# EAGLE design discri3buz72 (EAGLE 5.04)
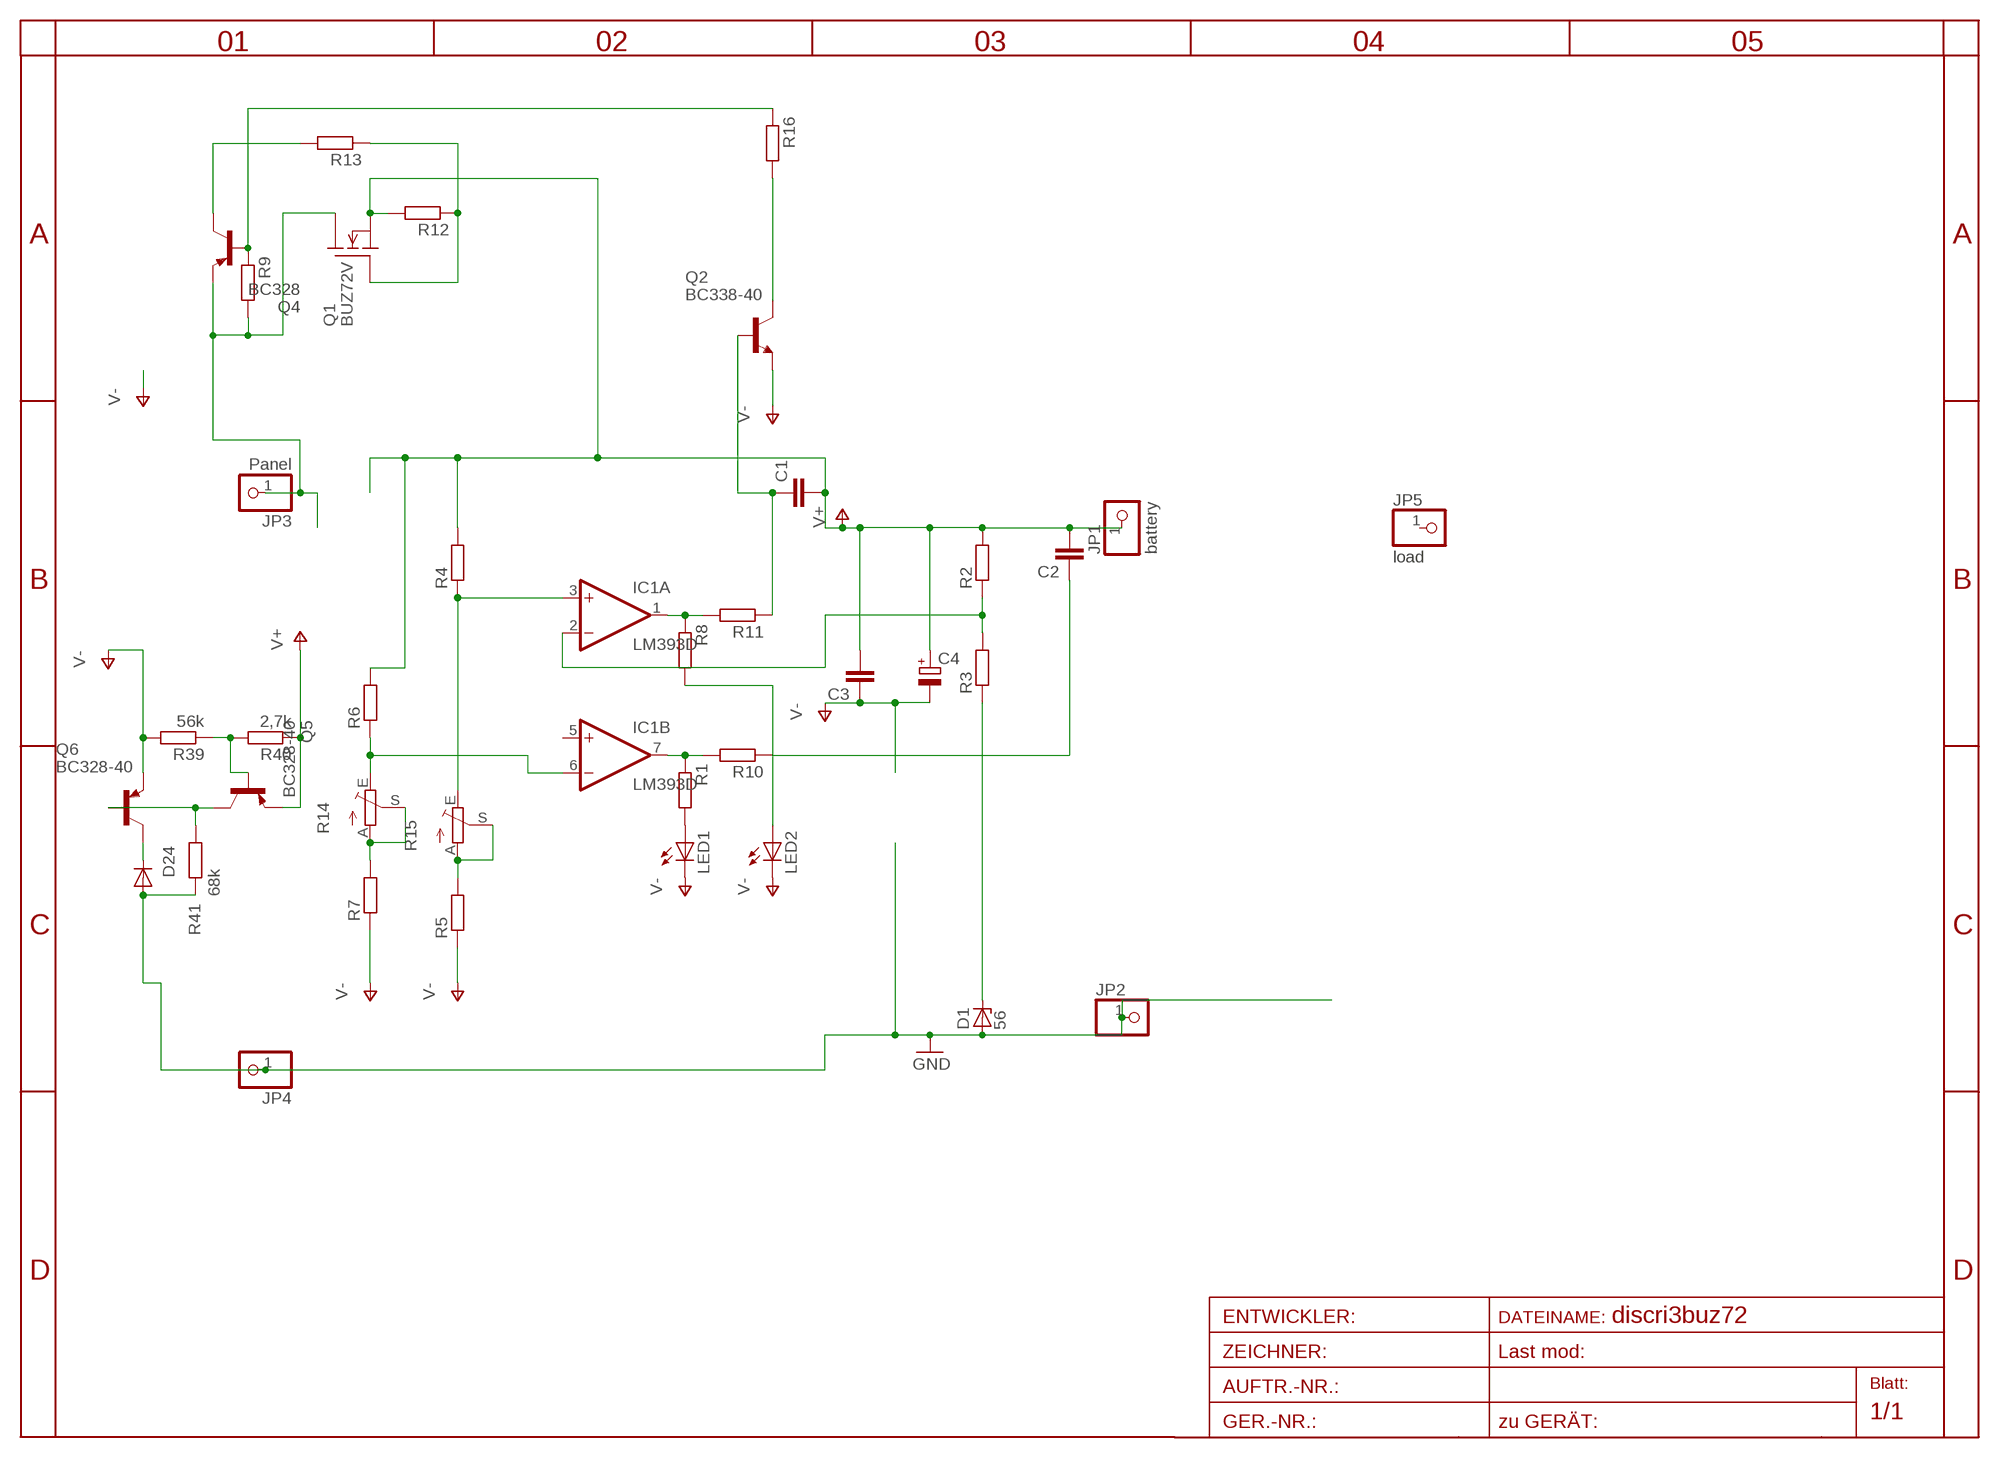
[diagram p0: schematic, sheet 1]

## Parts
C1  C-EU025-025X050  [C025-025X050]
C2  C-EU025-025X050  [C025-025X050]
C3  C-EU025-025X050  [C025-025X050]
C4  CPOL-EU5-13  [2,5-5-FLAT]
D1  56  ZENER-DIODEDO35Z10  [DO35Z10]
D24  Z20  DIODE-D-7.5  [D-7.5]
IC1  LM393D  [SO08]
JP1  battery  PINHD-1X1  [1X01]
JP2  PINHD-1X1  [1X01]
JP3  Panel  PINHD-1X1  [1X01]
JP4  PINHD-1X1  [1X01]
JP5  load  PINHD-1X1  [1X01]
LED1  LED3MM  [LED3MM]
LED2  LED3MM  [LED3MM]
Q1  BUZ72V  [TO220V]
Q2  BC338-40  [TO92-EBC]
Q4  BC328  [TO92-EBC]
Q5  BC328-40  [TO92-EBC]
Q6  BC328-40  [TO92-EBC]
R1  R-EU_0207/10  [0207/10]
R2  R-EU_0204/7  [0204/7]
R3  R-EU_0204/7  [0204/7]
R4  R-EU_0204/7  [0204/7]
R5  R-EU_0204/7  [0204/7]
R6  R-EU_0204/7  [0204/7]
R7  R-EU_0204/7  [0204/7]
R8  R-EU_0207/15  [0207/15]
R9  R-EU_0204/7  [0204/7]
R10  R-EU_0204/7  [0204/7]
R11  R-EU_0204/7  [0204/7]
R12  R-EU_0204/7  [0204/7]
R13  R-EU_0204/7  [0204/7]
R14  TRIM_EU-CA6V  [CA6V]
R15  TRIM_EU-CA6V  [CA6V]
R16  R-EU_0204/7  [0204/7]
R39  56k  R-EU_0204/7  [0204/7]
R40  2,7k  R-EU_0204/7  [0204/7]
R41  68k  R-EU_0207/10  [0207/10]

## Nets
GND: D1.A D24.A JP2.1 JP4.1 R41.2
N$1: D1.C R3.1
N$2: IC1.6(B:-IN) R6.1 R14.E
N$3: R7.2 R14.A R14.S
N$4: IC1.2(A:-IN) R2.1 R3.2
N$5: C1.1 Q2.B R11.1
N$6: LED1.A R1.2
N$7: LED2.A R8.2
N$8: Q2.C R16.2
N$11: R5.2 R15.A R15.S
N$12: IC1.3(A:+IN) R4.1 R15.E
N$13: D24.C Q6.C
N$14: IC1.1(A:OUT) R8.1 R11.2
N$15: IC1.7(B:OUT) R1.1 R10.2
N$16: Q4.B R9.1 R16.1
N$17: C2.1 R10.1
N$19: Q1.1(G) R12.1 R13.1
N$20: Q4.C R13.2
N$38: Q5.C Q6.B R41.1
N$41: Q5.B R39.1 R40.2
PANEL: JP3.1 Q1.2(D) Q4.E R9.2
V+: C1.2 C2.2 C3.2 C4.+ JP1.1 Q1.3(S) Q5.E R2.2 R4.2 R6.2 R12.2 R40.1
V-: C3.1 C4.- LED1.K(C) LED2.K(C) Q2.E Q6.E R5.1 R7.1 R39.2
Unconnected: IC1.5(B:+IN) JP5.1

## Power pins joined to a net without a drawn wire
V+: IC1.8(P:V+)
V-: IC1.4(P:V-)

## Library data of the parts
C1-C3 = rcl-2:C-EU: CAPACITOR, European symbol
C4 = rcl-2:CPOL-EU: POLARIZED CAPACITOR, European symbol
D1 = diode-1:ZENER-DIODE: Z-Diode
D24 = diode-1:DIODE-: DIODE
IC1 = linear:LM393: COMPARATOR
JP1-JP5 = pinhead:PINHD-1X1: PIN HEADER
LED1 LED2 = led:LED: LED
Q1 = transistor-fet:BUZ72: N-Channel Enhancement MOSFET 100V; 10A; 0,2Ohm
Q2 = transistor-npn:BC338*: NPN Transistor
Q4-Q6 = transistor-pnp:BC328*: PNP Transistror
R1-R13 R16 R39-R41 = rcl-2:R-EU_: RESISTOR, European symbol
R14 R15 = pot:TRIM_EU-: POTENTIOMETER

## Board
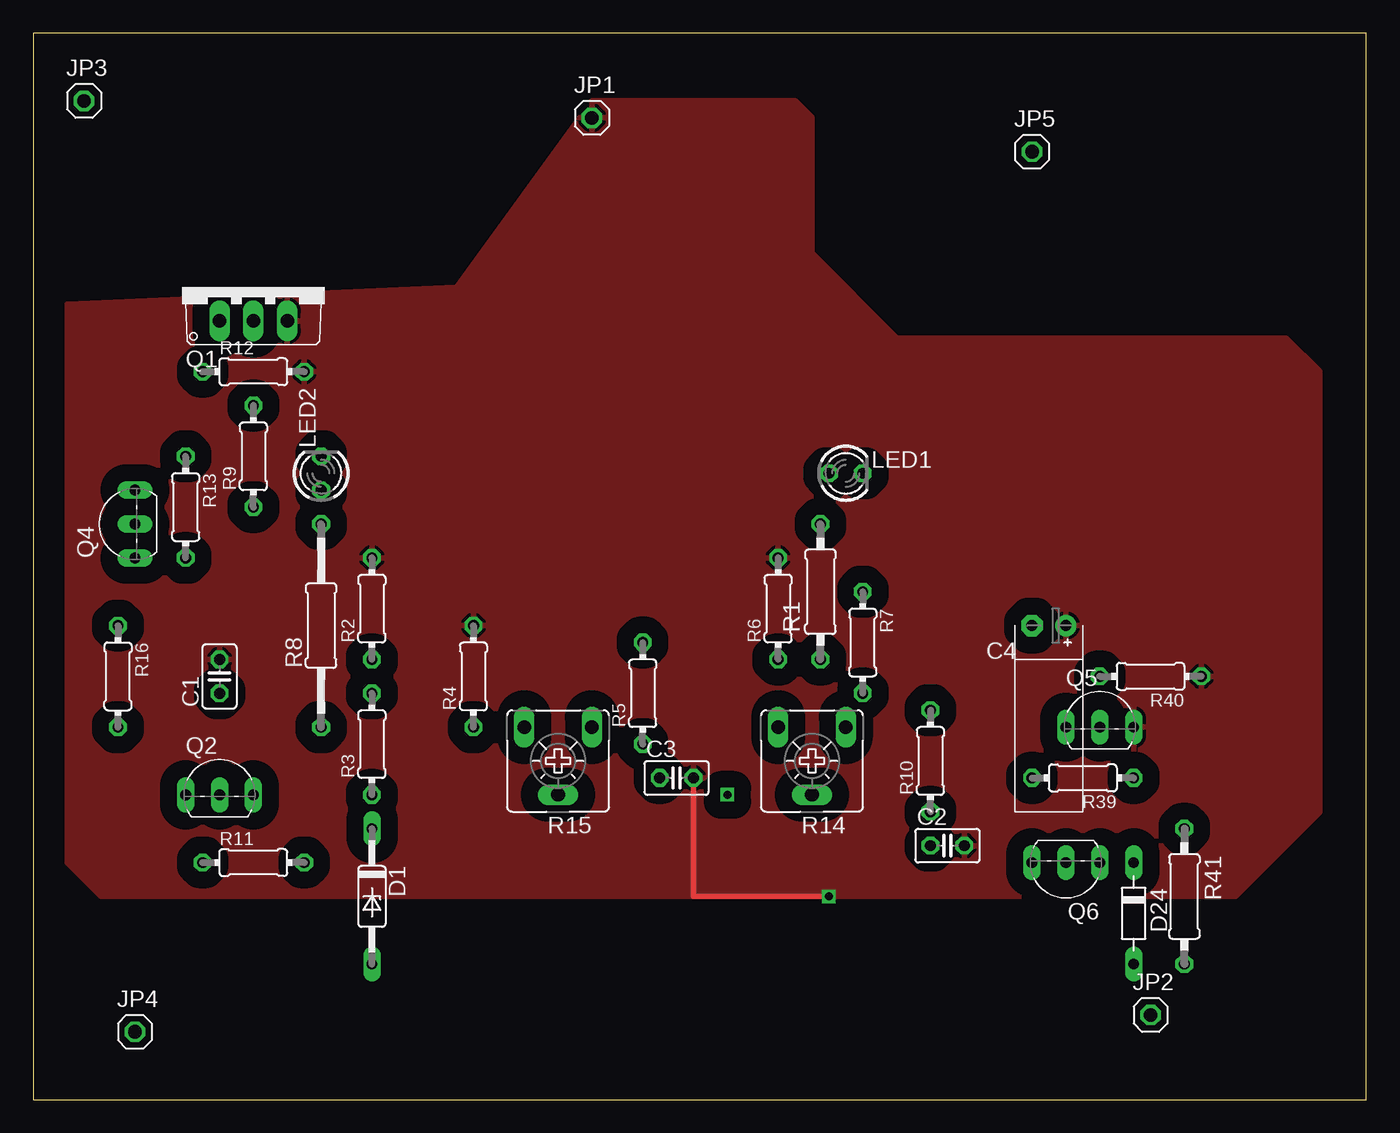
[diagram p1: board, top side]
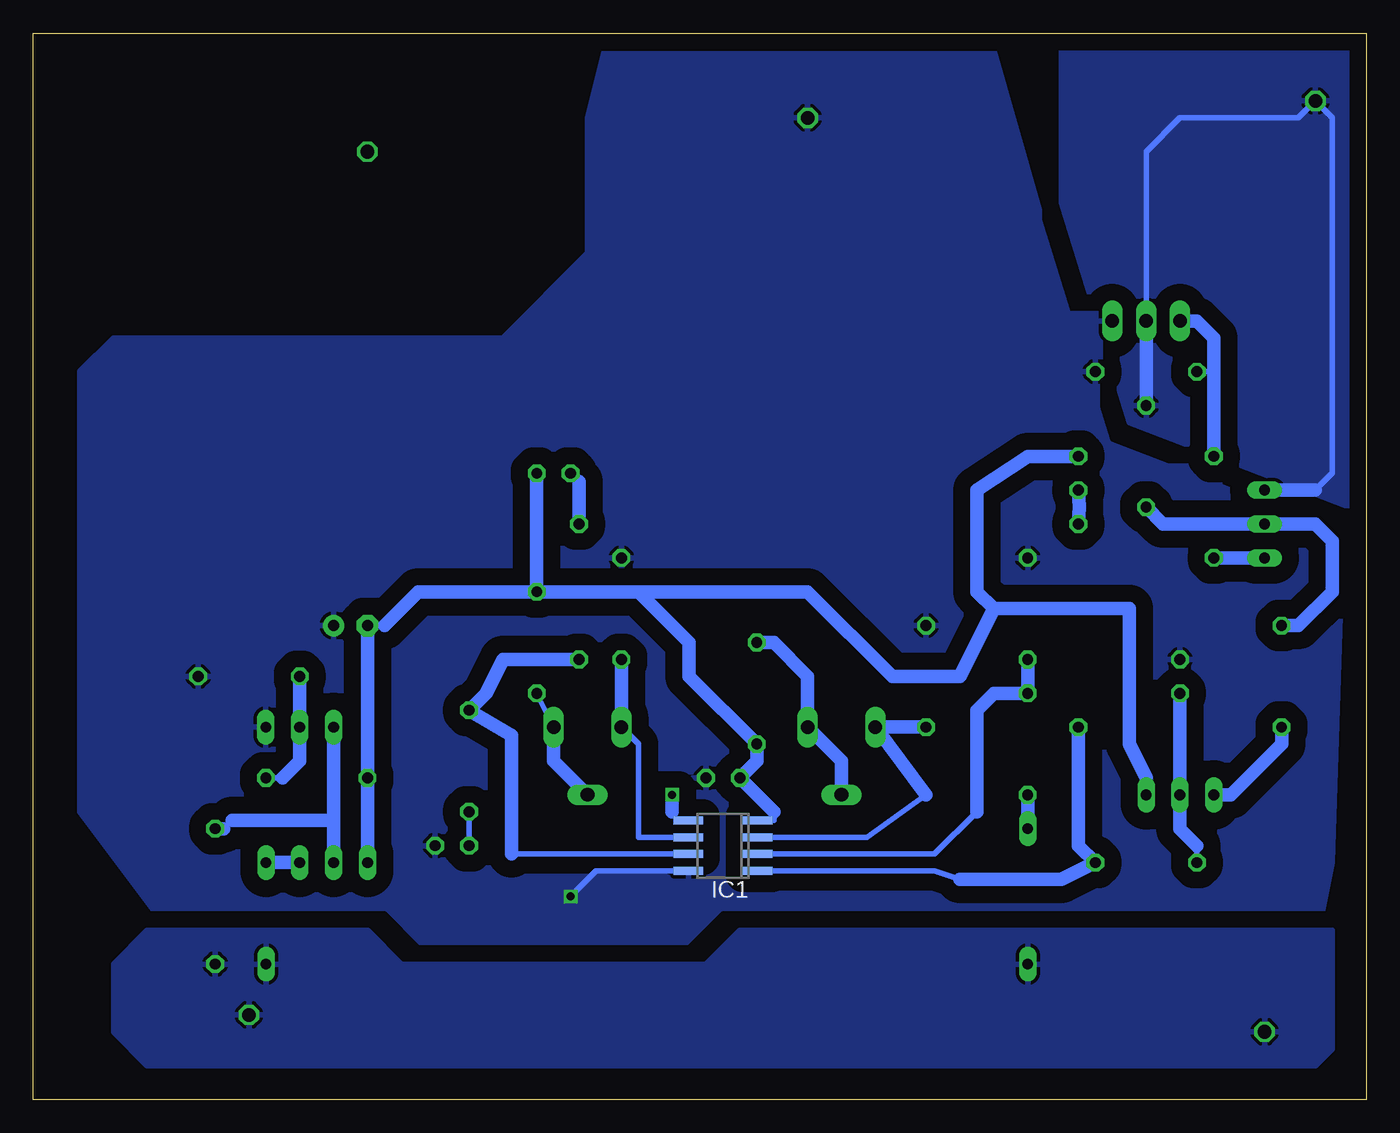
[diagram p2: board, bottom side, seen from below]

Size 100 x 80 mm. Coordinates in mm from the lower left corner, seen from the top.
Outline: 0,0 100,0 100,80 0,80 0,0
Copper layers (1*16): Top 0.035mm / dielectric 1.5mm / Bottom 0.035mm
Design rules "default": minimum track width 10mil, minimum drill 24mil, track to track 8mil, track to pad 8mil, pad to pad 8mil, via to via 8mil, smd to smd 8mil, copper to edge 40mil, drill to drill 8mil, minimum pad ring 10mil, minimum via ring 8mil, stop-mask expansion 4mil, vias tented up to drill 0mil, thermal gap 10mil

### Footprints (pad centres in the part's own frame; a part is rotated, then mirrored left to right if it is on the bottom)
C025-025X050 = drill 0.813 octagon: 1 -1.27,0; 2 1.27,0
2,5-5-FLAT = drill 0.813 pad 1.6 round: + -1.27,0 | drill 0.813 pad 1.6 octagon: - 1.27,0
DO35Z10 = drill 0.813 long: A 5.08,0; C -5.08,0
D-7.5 = drill 0.813 long: A 3.81,0; C -3.81,0
SO08 = smd 0.6 x 2.2: 1 -1.905,-2.6; 2 -0.635,-2.6; 3 0.635,-2.6; 4 1.905,-2.6; 5 1.905,2.6; 6 0.635,2.6; 7 -0.635,2.6; 8 -1.905,2.6
1X01 = drill 1.016 octagon: 1 0,0
LED3MM = drill 0.813 octagon: A -1.27,0; K 1.27,0
TO220V = drill 1.016 long: 1 -2.54,-2.54; 2 0,-2.54; 3 2.54,-2.54
TO92-EBC = drill 0.813 long: B 0,-1.27; C -2.54,-1.27; E 2.54,-1.27
0207/10 = drill 0.813 octagon: 1 -5.08,0; 2 5.08,0
0204/7 = drill 0.813 octagon: 1 -3.81,0; 2 3.81,0
0207/15 = drill 0.813 octagon: 1 -7.62,0; 2 7.62,0
CA6V = drill 1.016 long: A -2.54,-2.54; E 2.54,-2.54; S 0,2.54

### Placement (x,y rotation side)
C1  13.97,31.75 90 top
C2  68.58,19.05 0 top
C3  48.26,24.13 0 top
C4  76.2,35.56 180 top
D1  25.4,15.24 270 top
D24  82.55,13.97 270 top
IC1  48.26,19.05 90 bottom
JP1  41.91,73.66 0 top
JP2  83.82,6.35 0 top
JP3  3.81,74.93 0 top
JP4  7.62,5.08 0 top
JP5  74.93,71.12 0 top
LED1  60.96,46.99 0 top
LED2  21.59,46.99 90 top
Q1  16.51,60.96 0 top
Q2  13.97,24.13 0 top
Q4  6.35,43.18 90 top
Q5  80.01,29.21 0 top
Q6  77.47,16.51 180 top
R1  59.05,38.1 90 top
R2  25.4,36.83 90 top
R3  25.4,26.67 90 top
R4  33.02,31.75 90 top
R5  45.72,30.48 90 top
R6  55.88,36.83 90 top
R7  62.23,34.29 270 top
R8  21.59,35.56 90 top
R9  16.51,48.26 90 top
R10  67.31,25.4 90 top
R11  16.51,17.78 0 top
R12  16.51,54.61 0 top
R13  11.43,44.45 270 top
R14  58.42,25.4 180 top
R15  39.37,25.4 180 top
R16  6.35,31.75 270 top
R39  78.74,24.13 180 top
R40  83.82,31.75 180 top
R41  86.36,15.24 270 top

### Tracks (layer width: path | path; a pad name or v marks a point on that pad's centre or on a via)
GND
  pour Bottom (isolate 1.27, rank 4): 2.54,12.7 46.99,12.7 49.53,10.16 72.39,10.16 74.93,12.7 91.44,12.7 93.98,10.16 93.98,5.08 91.44,2.54 3.81,2.54 2.54,3.81
N$1
  Bottom 1.016: D1.C R3.1
N$2
  Bottom 0.406: IC1.6 54.61,19.68 54.61,26.67 R14.E
  Bottom 1.016: R14.E R6.1
N$3
  Bottom 0.406: R14.A R7.2
  Bottom 1.016: R14.S 60.96,25.4 R14.A
N$4
  Bottom 0.406: IC1.2 32.38,18.41 29.21,21.59
  Bottom 1.016: 29.21,21.59 29.21,29.21 27.94,30.48 R3.2 R2.1
N$5
  Bottom 0.406: R11.1 12.7,19.05
  Bottom 1.016: 12.7,19.05 13.97,20.32 Q2.B C1.1
N$6
  Bottom 0.406: 59.05,46.35 LED1.A
  Bottom 1.016: R1.2 59.05,46.35
N$7
  Bottom 1.016: LED2.A 21.51,44.45 R8.2
N$8
  Bottom 1.016: Q2.C 10.16,22.86 6.35,26.67 R16.2
N$9  (via drill 0.6)
  Bottom 1.016: 52.07,21.59 v52.07,22.86
N$11
  Bottom 1.016: R15.S 39.37,25.4 R15.A 41.91,31.75 44.45,34.29 R5.2
N$12
  Bottom 0.406: IC1.3 37.47,19.68 33.02,22.86
  Bottom 1.016: R4.1 R15.E 33.02,22.86
N$13
  Bottom 1.016: Q6.C D24.C
N$14
  Bottom 0.406: IC1.1 32.38,17.14 30.48,16.51
  Bottom 1.016: 30.48,16.51 22.86,16.51 R11.2 21.59,19.05 R8.1
N$15
  Bottom 0.406: IC1.7 64.14,18.41
  Bottom 1.016: 64.14,18.41 64.14,27.3 R10.2 66.04,30.48 64.77,33.02 R1.1
N$16
  Bottom 1.016: R16.1 5.08,35.56 2.54,38.1 2.54,41.91 3.81,43.18 Q4.B 15.24,43.18 R9.1
N$17
  Bottom 0.406: C2.1 R10.1
N$19
  Bottom 0.406: 11.43,54.61 R12.1
  Bottom 1.016: R13.1 11.43,54.61 11.43,57.15 12.7,58.42 Q1.1
N$20
  Bottom 1.016: Q4.C R13.2
N$38
  Bottom 0.406: 85.09,20.95 85.72,20.32
  Bottom 1.016: 85.72,20.32 R41.1 | 77.47,20.95 85.09,20.95 | Q6.B 77.47,20.95 | 77.47,20.95 Q5.C
N$41
  Bottom 0.406: R39.1 81.28,24.13
  Bottom 1.016: 81.28,24.13 80.01,25.4 Q5.B R40.2
PANEL
  Bottom 0.406: 3.81,45.72 2.54,46.99 2.54,73.66 JP3.1 5.08,73.66 13.97,73.66 16.51,71.12 Q1.2
  Bottom 1.016: 3.81,45.72 Q4.E | Q1.2 R9.2
  pour Bottom (isolate 1.27): 0,80.01 0,62.23 1.27,44.45 17.78,50.8 22.86,67.31 22.86,78.74 15.24,80.01
V+  (via drill 0.6)
  Top 0.406: v59.69,15.24 49.53,15.24 49.53,19.05 C3.2
  Bottom 0.406: IC1.8 57.78,17.14 v59.69,15.24
  pour Bottom (isolate 1.27, rank 5): 27.94,78.74 57.15,78.74 58.42,73.66 58.42,63.5 64.77,57.15 93.98,57.15 96.52,54.61 96.52,21.59 88.9,11.43 3.81,11.43 2.54,17.78 1.27,57.15 22.86,60.96
  pour Top (isolate 1.27, rank 5): 41.91,74.93 57.15,74.93 58.42,73.66 58.42,63.5 64.77,57.15 93.98,57.15 96.52,54.61 96.52,21.59 90.17,15.24 5.08,15.24 2.54,17.78 2.54,59.69 31.75,60.96
V-
  Bottom 0.406: 73.66,35.56 C4.- | 44.45,21.59 44.45,20.95 IC1.4 | Q2.E 16.51,24.13
  Bottom 1.016: Q6.E R39.2 C4.- | 73.66,35.56 71.12,38.1 R7.1 | 54.61,38.1 R7.1 | 54.61,38.1 50.8,34.29 50.8,31.75 R5.1 45.72,25.4 C3.1 44.45,21.59 | 16.51,24.13 17.78,26.67 17.78,36.83 27.94,36.83 | 27.94,36.83 30.48,31.75 35.56,31.75 41.91,38.1 54.61,38.1 | LED2.K 25.4,48.26 29.21,45.72 29.21,38.1 27.94,36.83 | R7.1 LED1.K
